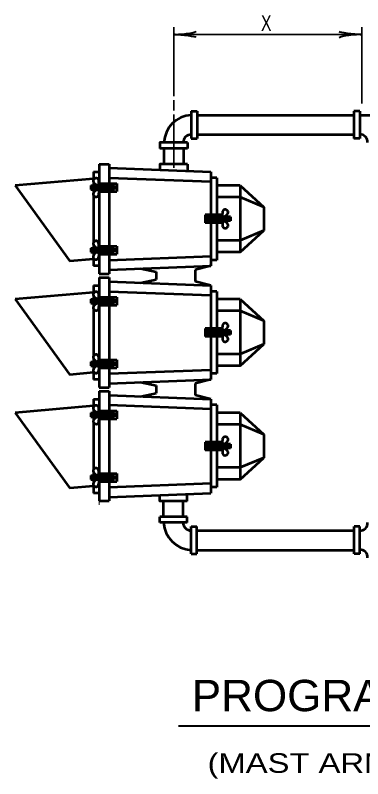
# Model space of a CAD drawing. Extents: x -370 to 486, y -203 to 341.
# Drawn here: x 133.3 to 186.5, y -16.9 to 100 of the extents above; entities that cross this region are included whole.
import ezdxf
from ezdxf.enums import TextEntityAlignment as Align

# ---------------------------------------------------------------- set-up
doc = ezdxf.new("R2010")
doc.units = 0
doc.header["$LTSCALE"] = 0.96
doc.layers.add('1', color=7, linetype='Continuous', lineweight=53)

msp = doc.modelspace()

# ---------------------------------------------------------------- linework, layer by layer
at = {"layer": '1', "lineweight": 35}
for p, q in [((157.5789, 98.1642), (157.5789, 87.6184)), ((186.3789, 98.1642), (186.3789, 86.455)), ((157.5789, 97.0382), (186.3789, 97.0382)), ((157.5789, 86.9742), (157.5789, 85.404)), ((157.5789, 84.8001), (157.5789, 76.6272))]:
    msp.add_line(p, q, dxfattribs=at)
at = {"layer": '1'}
for p, q in [((160.2789, 85.303), (160.2789, 81.103)), ((160.2789, 85.303), (161.1789, 85.303)), ((161.1789, 85.303), (161.1789, 81.103)), ((161.1789, 84.703), (185.1535, 84.703)), ((185.1535, 85.303), (185.1535, 81.103)), ((186.0535, 85.303), (185.1535, 85.303)), ((186.0535, 85.303), (186.0535, 81.103)), ((186.0535, 84.703), (191.2011, 84.703)), ((160.2789, 81.103), (161.1789, 81.103)), ((161.1789, 81.703), (185.1535, 81.703)), ((186.0535, 81.103), (185.1535, 81.103)), ((159.6789, 79.603), (155.4789, 79.603)), ((156.0789, 79.603), (156.0789, 77.203)), ((159.0789, 79.603), (159.0789, 77.203)), ((159.6789, 80.503), (159.6789, 79.603)), ((146.1789, 77.203), (147.6789, 77.203)), ((146.1789, 77.203), (146.1789, 74.203)), ((147.6789, 77.203), (147.6789, 74.203)), ((157.5789, 77.203), (157.5789, 77.1891)), ((159.6789, 77.203), (159.6789, 76.1415)), ((145.2789, 76.003), (146.1789, 76.003)), ((145.2789, 76.003), (145.2789, 74.7359)), ((147.6789, 76.603), (163.2789, 76.003)), ((163.2789, 76.003), (163.2789, 69.403)), ((145.2789, 74.953), (133.3246, 73.9071)), ((147.6789, 75.102), (163.2789, 74.502)), ((164.1789, 75.103), (163.2789, 75.103)), ((164.1789, 75.103), (164.1789, 69.403)), ((133.3246, 73.9071), (141.6926, 62.3392)), ((144.8916, 73.9042), (144.8916, 73.3042)), ((144.8916, 73.9042), (148.4916, 73.9042)), ((145.0416, 73.7542), (145.0416, 73.4542)), ((145.1916, 73.9042), (145.1916, 73.3042)), ((145.2789, 74.4457), (145.2789, 73.9042)), ((145.3416, 73.7542), (145.3416, 73.4542)), ((145.8098, 73.9042), (145.3827, 74.2812)), ((145.4916, 73.9042), (145.4916, 73.3042)), ((145.6416, 73.7542), (145.6416, 73.4542)), ((145.7916, 73.9042), (145.7916, 73.3042)), ((145.9416, 73.7542), (145.9416, 73.4542)), ((146.0587, 73.9042), (146.1045, 74.4477)), ((146.0916, 73.9042), (146.0916, 73.3042)), ((146.1789, 74.203), (148.8789, 74.203)), ((146.2416, 73.7542), (146.2416, 73.4542)), ((146.3916, 73.9042), (146.3916, 73.3042)), ((146.5416, 73.7542), (146.5416, 73.4542)), ((146.6916, 73.9042), (146.6916, 73.3042)), ((146.8416, 73.7542), (146.8416, 73.4542)), ((146.9916, 73.9042), (146.9916, 73.3042)), ((147.1416, 73.7542), (147.1416, 73.4542)), ((147.2916, 73.9042), (147.2916, 73.3042)), ((147.4416, 73.7542), (147.4416, 73.4542)), ((147.5916, 73.9042), (147.5916, 73.3042)), ((147.7416, 73.7542), (147.7416, 73.4542)), ((147.8916, 73.9042), (147.8916, 73.3042)), ((148.0416, 73.7542), (148.0416, 73.4542)), ((148.1916, 73.9042), (148.1916, 73.3042)), ((148.3416, 73.7542), (148.3416, 73.4542)), ((148.4916, 73.9042), (148.4916, 73.3042)), ((148.8789, 74.203), (148.8789, 73.003)), ((167.7789, 73.903), (164.1789, 73.903)), ((167.7789, 73.903), (167.7789, 63.703)), ((167.7789, 73.903), (171.3789, 70.603)), ((144.8916, 73.3042), (148.4916, 73.3042)), ((145.2789, 73.3042), (145.2789, 72.7641)), ((145.8098, 73.3056), (145.3827, 72.9286)), ((146.0587, 73.3056), (146.1045, 72.7621)), ((146.1789, 73.003), (148.8789, 73.003)), ((146.1789, 73.003), (146.1789, 64.603)), ((147.6789, 73.003), (147.6789, 64.603)), ((145.2789, 72.4739), (145.2789, 65.1543)), ((167.7789, 72.103), (164.1789, 72.103)), ((171.3789, 70.603), (167.7789, 72.103)), ((171.3789, 70.603), (171.3789, 67.003)), ((165.0865, 69.403), (162.3789, 69.403)), ((162.3789, 69.403), (162.3789, 68.203)), ((166.2789, 69.103), (162.6789, 69.103)), ((162.6789, 69.103), (162.6789, 68.503)), ((162.9789, 69.103), (162.9789, 68.503)), ((163.2789, 69.103), (163.2789, 68.503)), ((163.5789, 69.103), (163.5789, 68.503)), ((163.8789, 69.103), (163.8789, 68.503)), ((164.1789, 69.103), (164.1789, 68.503)), ((164.4789, 69.103), (164.4789, 68.503)), ((164.7789, 69.103), (164.7789, 68.503)), ((165.1118, 69.103), (165.066, 69.6465)), ((165.0789, 69.103), (165.0789, 68.503)), ((165.3607, 69.103), (165.7878, 69.48)), ((165.3789, 69.103), (165.3789, 68.503)), ((165.6789, 69.103), (165.6789, 68.503)), ((165.9789, 69.103), (165.9789, 68.503)), ((166.2789, 69.103), (166.2789, 68.503)), ((165.0789, 68.203), (162.3789, 68.203)), ((166.2789, 68.503), (162.6789, 68.503)), ((162.8289, 68.953), (162.8289, 68.653)), ((163.1289, 68.953), (163.1289, 68.653)), ((163.2789, 68.203), (163.2789, 61.603)), ((163.4289, 68.953), (163.4289, 68.653)), ((163.7289, 68.953), (163.7289, 68.653)), ((163.8789, 68.953), (163.8789, 68.653)), ((164.0289, 68.953), (164.0289, 68.653)), ((164.1789, 68.203), (164.1789, 62.503)), ((164.3289, 68.953), (164.3289, 68.653)), ((164.6289, 68.953), (164.6289, 68.653)), ((164.9289, 68.953), (164.9289, 68.653)), ((165.1118, 68.5044), (165.066, 67.9609)), ((165.2289, 68.953), (165.2289, 68.653)), ((165.3607, 68.5044), (165.7878, 68.1274)), ((165.5289, 68.953), (165.5289, 68.653)), ((165.8289, 68.953), (165.8289, 68.653)), ((166.1289, 68.953), (166.1289, 68.653)), ((167.7789, 63.703), (171.3789, 67.003)), ((171.3789, 67.003), (167.7789, 65.503)), ((167.7789, 65.503), (164.1789, 65.503)), ((145.2789, 64.8241), (145.2789, 64.3026)), ((145.8022, 64.3026), (145.3751, 64.6796)), ((146.0511, 64.3026), (146.0969, 64.8461)), ((146.1789, 64.603), (148.8789, 64.603)), ((148.8789, 64.603), (148.8789, 63.403)), ((144.884, 64.3026), (144.884, 63.7026)), ((144.884, 64.3026), (148.484, 64.3026)), ((144.884, 63.7026), (148.484, 63.7026)), ((145.034, 64.1526), (145.034, 63.8526)), ((145.184, 64.3026), (145.184, 63.7026)), ((145.2789, 63.7026), (145.2789, 63.1825)), ((145.334, 64.1526), (145.334, 63.8526)), ((145.8022, 63.704), (145.3751, 63.327)), ((145.484, 64.3026), (145.484, 63.7026)), ((145.634, 64.1526), (145.634, 63.8526)), ((145.784, 64.3026), (145.784, 63.7026)), ((145.934, 64.1526), (145.934, 63.8526)), ((146.0511, 63.704), (146.0969, 63.1605)), ((146.084, 64.3026), (146.084, 63.7026)), ((146.1789, 63.403), (148.8789, 63.403)), ((146.1789, 63.403), (146.1789, 60.403)), ((146.234, 64.1526), (146.234, 63.8526)), ((146.384, 64.3026), (146.384, 63.7026)), ((146.534, 64.1526), (146.534, 63.8526)), ((146.684, 64.3026), (146.684, 63.7026)), ((146.834, 64.1526), (146.834, 63.8526)), ((146.984, 64.3026), (146.984, 63.7026)), ((147.134, 64.1526), (147.134, 63.8526)), ((147.284, 64.3026), (147.284, 63.7026)), ((147.434, 64.1526), (147.434, 63.8526)), ((147.584, 64.3026), (147.584, 63.7026)), ((147.6789, 63.403), (147.6789, 60.403)), ((147.734, 64.1526), (147.734, 63.8526)), ((147.884, 64.3026), (147.884, 63.7026)), ((148.034, 64.1526), (148.034, 63.8526)), ((148.184, 64.3026), (148.184, 63.7026)), ((148.334, 64.1526), (148.334, 63.8526)), ((148.484, 64.3026), (148.484, 63.7026)), ((167.7789, 63.703), (164.1789, 63.703)), ((145.2789, 62.653), (141.6926, 62.3392)), ((145.2789, 62.8523), (145.2789, 61.603)), ((147.6789, 62.5041), (163.2789, 63.1041)), ((164.1789, 62.503), (163.2789, 62.503)), ((146.1789, 61.603), (145.2789, 61.603)), ((147.6789, 61.003), (163.2789, 61.603)), ((152.4753, 61.1875), (154.8777, 60.703)), ((163.2789, 61.603), (160.8777, 61.003)), ((160.8777, 61.003), (160.8777, 59.203)), ((146.1789, 60.403), (147.6789, 60.403)), ((146.1789, 59.803), (147.6789, 59.803)), ((146.1789, 59.803), (146.1789, 56.803)), ((147.6789, 59.803), (147.6789, 56.803)), ((154.8777, 60.703), (154.8777, 59.503)), ((145.2789, 58.603), (146.1789, 58.603)), ((145.2789, 58.603), (145.2789, 57.3359)), ((147.6789, 59.2031), (163.2789, 58.603)), ((152.4753, 59.0186), (154.8777, 59.503)), ((163.2789, 58.603), (160.8777, 59.203)), ((163.2789, 58.603), (163.2789, 52.003)), ((145.2789, 57.553), (133.3246, 56.5071)), ((147.6789, 57.702), (163.2789, 57.102)), ((164.1789, 57.703), (163.2789, 57.703)), ((164.1789, 57.703), (164.1789, 52.003)), ((133.3246, 56.5071), (141.6926, 44.9392)), ((144.8916, 56.5042), (144.8916, 55.9042)), ((144.8916, 56.5042), (148.4916, 56.5042)), ((145.0416, 56.3542), (145.0416, 56.0542)), ((145.1916, 56.5042), (145.1916, 55.9042)), ((145.2789, 57.0457), (145.2789, 56.5042)), ((145.3416, 56.3542), (145.3416, 56.0542)), ((145.8098, 56.5042), (145.3827, 56.8812)), ((145.4916, 56.5042), (145.4916, 55.9042)), ((145.6416, 56.3542), (145.6416, 56.0542)), ((145.7916, 56.5042), (145.7916, 55.9042)), ((145.9416, 56.3542), (145.9416, 56.0542)), ((146.0587, 56.5042), (146.1045, 57.0477)), ((146.0916, 56.5042), (146.0916, 55.9042)), ((146.1789, 56.803), (148.8789, 56.803)), ((146.2416, 56.3542), (146.2416, 56.0542)), ((146.3916, 56.5042), (146.3916, 55.9042)), ((146.5416, 56.3542), (146.5416, 56.0542)), ((146.6916, 56.5042), (146.6916, 55.9042)), ((146.8416, 56.3542), (146.8416, 56.0542)), ((146.9916, 56.5042), (146.9916, 55.9042)), ((147.1416, 56.3542), (147.1416, 56.0542)), ((147.2916, 56.5042), (147.2916, 55.9042)), ((147.4416, 56.3542), (147.4416, 56.0542)), ((147.5916, 56.5042), (147.5916, 55.9042)), ((147.7416, 56.3542), (147.7416, 56.0542)), ((147.8916, 56.5042), (147.8916, 55.9042)), ((148.0416, 56.3542), (148.0416, 56.0542)), ((148.1916, 56.5042), (148.1916, 55.9042)), ((148.3416, 56.3542), (148.3416, 56.0542)), ((148.4916, 56.5042), (148.4916, 55.9042)), ((148.8789, 56.803), (148.8789, 55.603)), ((167.7789, 56.503), (164.1789, 56.503)), ((167.7789, 56.503), (167.7789, 46.303)), ((167.7789, 56.503), (171.3789, 53.203)), ((144.8916, 55.9042), (148.4916, 55.9042)), ((145.2789, 55.9042), (145.2789, 55.3641)), ((145.2789, 55.0739), (145.2789, 47.7543)), ((145.8098, 55.9056), (145.3827, 55.5286)), ((146.0587, 55.9056), (146.1045, 55.3621)), ((146.1789, 55.603), (148.8789, 55.603)), ((146.1789, 55.603), (146.1789, 47.203)), ((147.6789, 55.603), (147.6789, 47.203)), ((167.7789, 54.703), (164.1789, 54.703)), ((171.3789, 53.203), (167.7789, 54.703)), ((171.3789, 53.203), (171.3789, 49.603)), ((165.0865, 52.003), (162.3789, 52.003)), ((162.3789, 52.003), (162.3789, 50.803)), ((166.2789, 51.703), (162.6789, 51.703)), ((162.6789, 51.703), (162.6789, 51.103)), ((162.8289, 51.553), (162.8289, 51.253)), ((162.9789, 51.703), (162.9789, 51.103)), ((163.1289, 51.553), (163.1289, 51.253)), ((163.2789, 51.703), (163.2789, 51.103)), ((163.4289, 51.553), (163.4289, 51.253)), ((163.5789, 51.703), (163.5789, 51.103)), ((163.7289, 51.553), (163.7289, 51.253)), ((163.8789, 51.703), (163.8789, 51.103)), ((163.8789, 51.553), (163.8789, 51.253)), ((164.0289, 51.553), (164.0289, 51.253)), ((164.1789, 51.703), (164.1789, 51.103)), ((164.3289, 51.553), (164.3289, 51.253)), ((164.4789, 51.703), (164.4789, 51.103)), ((164.6289, 51.553), (164.6289, 51.253)), ((164.7789, 51.703), (164.7789, 51.103)), ((164.9289, 51.553), (164.9289, 51.253)), ((165.1118, 51.703), (165.066, 52.2465)), ((165.0789, 51.703), (165.0789, 51.103)), ((165.2289, 51.553), (165.2289, 51.253)), ((165.3607, 51.703), (165.7878, 52.08)), ((165.3789, 51.703), (165.3789, 51.103)), ((165.5289, 51.553), (165.5289, 51.253)), ((165.6789, 51.703), (165.6789, 51.103)), ((165.8289, 51.553), (165.8289, 51.253)), ((165.9789, 51.703), (165.9789, 51.103)), ((166.1289, 51.553), (166.1289, 51.253)), ((166.2789, 51.703), (166.2789, 51.103)), ((165.0789, 50.803), (162.3789, 50.803)), ((166.2789, 51.103), (162.6789, 51.103)), ((163.2789, 50.803), (163.2789, 44.203)), ((164.1789, 50.803), (164.1789, 45.103)), ((165.1118, 51.1044), (165.066, 50.5609)), ((165.3607, 51.1044), (165.7878, 50.7274)), ((167.7789, 46.303), (171.3789, 49.603)), ((171.3789, 49.603), (167.7789, 48.103)), ((167.7789, 48.103), (164.1789, 48.103)), ((144.884, 46.9026), (144.884, 46.3026)), ((144.884, 46.9026), (148.484, 46.9026)), ((145.184, 46.9026), (145.184, 46.3026)), ((145.2789, 47.4241), (145.2789, 46.9026)), ((145.8022, 46.9026), (145.3751, 47.2796)), ((145.484, 46.9026), (145.484, 46.3026)), ((145.784, 46.9026), (145.784, 46.3026)), ((146.0511, 46.9026), (146.0969, 47.4461)), ((146.084, 46.9026), (146.084, 46.3026)), ((146.1789, 47.203), (148.8789, 47.203)), ((146.384, 46.9026), (146.384, 46.3026)), ((146.684, 46.9026), (146.684, 46.3026)), ((146.984, 46.9026), (146.984, 46.3026)), ((147.284, 46.9026), (147.284, 46.3026)), ((147.584, 46.9026), (147.584, 46.3026)), ((147.884, 46.9026), (147.884, 46.3026)), ((148.184, 46.9026), (148.184, 46.3026)), ((148.484, 46.9026), (148.484, 46.3026)), ((148.8789, 47.203), (148.8789, 46.003)), ((144.884, 46.3026), (148.484, 46.3026)), ((145.034, 46.7526), (145.034, 46.4526)), ((145.2789, 46.3026), (145.2789, 45.7825)), ((145.334, 46.7526), (145.334, 46.4526)), ((145.8022, 46.304), (145.3751, 45.927)), ((145.634, 46.7526), (145.634, 46.4526)), ((145.934, 46.7526), (145.934, 46.4526)), ((146.0511, 46.304), (146.0969, 45.7605)), ((146.1789, 46.003), (148.8789, 46.003)), ((146.1789, 46.003), (146.1789, 43.003)), ((146.234, 46.7526), (146.234, 46.4526)), ((146.534, 46.7526), (146.534, 46.4526)), ((146.834, 46.7526), (146.834, 46.4526)), ((147.134, 46.7526), (147.134, 46.4526)), ((147.434, 46.7526), (147.434, 46.4526)), ((147.6789, 46.003), (147.6789, 43.003)), ((147.6789, 45.1041), (163.2789, 45.7041)), ((147.734, 46.7526), (147.734, 46.4526)), ((148.034, 46.7526), (148.034, 46.4526)), ((148.334, 46.7526), (148.334, 46.4526)), ((167.7789, 46.303), (164.1789, 46.303)), ((145.2789, 45.253), (141.6926, 44.9392)), ((145.2789, 45.4523), (145.2789, 44.203)), ((164.1789, 45.103), (163.2789, 45.103)), ((146.1789, 44.203), (145.2789, 44.203)), ((147.6789, 43.603), (163.2789, 44.203)), ((152.4753, 43.7875), (154.8777, 43.303)), ((154.8777, 43.303), (154.8777, 42.103)), ((163.2789, 44.203), (160.8777, 43.603)), ((160.8777, 43.603), (160.8777, 41.803)), ((146.1789, 43.003), (147.6789, 43.003)), ((146.1789, 42.403), (147.6789, 42.403)), ((146.1789, 42.403), (146.1789, 39.403)), ((147.6789, 42.403), (147.6789, 39.403)), ((152.4753, 41.6186), (154.8777, 42.103)), ((145.2789, 41.203), (146.1789, 41.203)), ((145.2789, 41.203), (145.2789, 39.9359)), ((147.6789, 41.803), (163.2789, 41.203)), ((163.2789, 41.203), (160.8777, 41.803)), ((163.2789, 41.203), (163.2789, 34.603)), ((145.2789, 40.153), (133.3246, 39.1071)), ((147.6789, 40.302), (163.2789, 39.702)), ((164.1789, 40.303), (163.2789, 40.303)), ((164.1789, 40.303), (164.1789, 34.603)), ((133.3246, 39.1071), (141.6926, 27.5392)), ((144.8916, 39.1042), (144.8916, 38.5042)), ((144.8916, 39.1042), (148.4916, 39.1042)), ((145.0416, 38.9542), (145.0416, 38.6542)), ((145.1916, 39.1042), (145.1916, 38.5042)), ((145.2789, 39.6457), (145.2789, 39.1042)), ((145.3416, 38.9542), (145.3416, 38.6542)), ((145.8098, 39.1042), (145.3827, 39.4812)), ((145.4916, 39.1042), (145.4916, 38.5042)), ((145.6416, 38.9542), (145.6416, 38.6542)), ((145.7916, 39.1042), (145.7916, 38.5042)), ((145.9416, 38.9542), (145.9416, 38.6542)), ((146.0587, 39.1042), (146.1045, 39.6477)), ((146.0916, 39.1042), (146.0916, 38.5042)), ((146.1789, 39.403), (148.8789, 39.403)), ((146.2416, 38.9542), (146.2416, 38.6542)), ((146.3916, 39.1042), (146.3916, 38.5042)), ((146.5416, 38.9542), (146.5416, 38.6542)), ((146.6916, 39.1042), (146.6916, 38.5042)), ((146.8416, 38.9542), (146.8416, 38.6542)), ((146.9916, 39.1042), (146.9916, 38.5042)), ((147.1416, 38.9542), (147.1416, 38.6542)), ((147.2916, 39.1042), (147.2916, 38.5042)), ((147.4416, 38.9542), (147.4416, 38.6542)), ((147.5916, 39.1042), (147.5916, 38.5042)), ((147.7416, 38.9542), (147.7416, 38.6542)), ((147.8916, 39.1042), (147.8916, 38.5042)), ((148.0416, 38.9542), (148.0416, 38.6542)), ((148.1916, 39.1042), (148.1916, 38.5042)), ((148.3416, 38.9542), (148.3416, 38.6542)), ((148.4916, 39.1042), (148.4916, 38.5042)), ((148.8789, 39.403), (148.8789, 38.203)), ((167.7789, 39.103), (164.1789, 39.103)), ((167.7789, 39.103), (167.7789, 28.903)), ((167.7789, 39.103), (171.3789, 35.803)), ((144.8916, 38.5042), (148.4916, 38.5042)), ((145.2789, 38.5042), (145.2789, 37.9641)), ((145.2789, 37.6739), (145.2789, 30.3543)), ((145.8098, 38.5056), (145.3827, 38.1286)), ((146.0587, 38.5056), (146.1045, 37.9621)), ((146.1789, 38.203), (148.8789, 38.203)), ((146.1789, 38.203), (146.1789, 29.803)), ((147.6789, 38.203), (147.6789, 29.803)), ((167.7789, 37.303), (164.1789, 37.303)), ((171.3789, 35.803), (167.7789, 37.303)), ((171.3789, 35.803), (171.3789, 32.203)), ((165.0865, 34.603), (162.3789, 34.603)), ((162.3789, 34.603), (162.3789, 33.403)), ((166.2789, 34.303), (162.6789, 34.303)), ((162.6789, 34.303), (162.6789, 33.703)), ((162.8289, 34.153), (162.8289, 33.853)), ((162.9789, 34.303), (162.9789, 33.703)), ((163.1289, 34.153), (163.1289, 33.853)), ((163.2789, 34.303), (163.2789, 33.703)), ((163.4289, 34.153), (163.4289, 33.853)), ((163.5789, 34.303), (163.5789, 33.703)), ((163.7289, 34.153), (163.7289, 33.853)), ((163.8789, 34.303), (163.8789, 33.703)), ((163.8789, 34.153), (163.8789, 33.853)), ((164.0289, 34.153), (164.0289, 33.853)), ((164.1789, 34.303), (164.1789, 33.703)), ((164.3289, 34.153), (164.3289, 33.853)), ((164.4789, 34.303), (164.4789, 33.703)), ((164.6289, 34.153), (164.6289, 33.853)), ((164.7789, 34.303), (164.7789, 33.703)), ((164.9289, 34.153), (164.9289, 33.853)), ((165.1118, 34.303), (165.066, 34.8465)), ((165.0789, 34.303), (165.0789, 33.703)), ((165.2289, 34.153), (165.2289, 33.853)), ((165.3607, 34.303), (165.7878, 34.68)), ((165.3789, 34.303), (165.3789, 33.703)), ((165.5289, 34.153), (165.5289, 33.853)), ((165.6789, 34.303), (165.6789, 33.703)), ((165.8289, 34.153), (165.8289, 33.853)), ((165.9789, 34.303), (165.9789, 33.703)), ((166.1289, 34.153), (166.1289, 33.853)), ((166.2789, 34.303), (166.2789, 33.703)), ((165.0789, 33.403), (162.3789, 33.403)), ((166.2789, 33.703), (162.6789, 33.703)), ((163.2789, 33.403), (163.2789, 26.803)), ((164.1789, 33.403), (164.1789, 27.703)), ((165.1118, 33.7044), (165.066, 33.1609)), ((165.3607, 33.7044), (165.7878, 33.3274)), ((167.7789, 28.903), (171.3789, 32.203)), ((171.3789, 32.203), (167.7789, 30.703)), ((167.7789, 30.703), (164.1789, 30.703)), ((144.884, 29.5026), (144.884, 28.9026)), ((144.884, 29.5026), (148.484, 29.5026)), ((145.034, 29.3526), (145.034, 29.0526)), ((145.184, 29.5026), (145.184, 28.9026)), ((145.2789, 30.0241), (145.2789, 29.5026)), ((145.334, 29.3526), (145.334, 29.0526)), ((145.8022, 29.5026), (145.3751, 29.8796)), ((145.484, 29.5026), (145.484, 28.9026)), ((145.634, 29.3526), (145.634, 29.0526)), ((145.784, 29.5026), (145.784, 28.9026)), ((145.934, 29.3526), (145.934, 29.0526)), ((146.0511, 29.5026), (146.0969, 30.0461)), ((146.084, 29.5026), (146.084, 28.9026)), ((146.1789, 29.803), (148.8789, 29.803)), ((146.234, 29.3526), (146.234, 29.0526)), ((146.384, 29.5026), (146.384, 28.9026)), ((146.534, 29.3526), (146.534, 29.0526)), ((146.684, 29.5026), (146.684, 28.9026)), ((146.834, 29.3526), (146.834, 29.0526)), ((146.984, 29.5026), (146.984, 28.9026)), ((147.134, 29.3526), (147.134, 29.0526)), ((147.284, 29.5026), (147.284, 28.9026)), ((147.434, 29.3526), (147.434, 29.0526)), ((147.584, 29.5026), (147.584, 28.9026)), ((147.734, 29.3526), (147.734, 29.0526)), ((147.884, 29.5026), (147.884, 28.9026)), ((148.034, 29.3526), (148.034, 29.0526)), ((148.184, 29.5026), (148.184, 28.9026)), ((148.334, 29.3526), (148.334, 29.0526)), ((148.484, 29.5026), (148.484, 28.9026)), ((148.8789, 29.803), (148.8789, 28.603)), ((144.884, 28.9026), (148.484, 28.9026)), ((145.2789, 28.9026), (145.2789, 28.3825)), ((145.8022, 28.904), (145.3751, 28.527)), ((146.0511, 28.904), (146.0969, 28.3605)), ((146.1789, 28.603), (148.8789, 28.603)), ((146.1789, 28.603), (146.1789, 25.603)), ((147.6789, 28.603), (147.6789, 25.603)), ((147.6789, 27.7041), (163.2789, 28.3041)), ((167.7789, 28.903), (164.1789, 28.903)), ((145.2789, 27.853), (141.6926, 27.5392)), ((145.2789, 28.0523), (145.2789, 26.803)), ((164.1789, 27.703), (163.2789, 27.703)), ((146.1789, 26.803), (145.2789, 26.803)), ((147.6789, 26.203), (163.2789, 26.803)), ((159.6435, 25.5897), (159.6435, 26.6512)), ((146.1789, 25.603), (147.6789, 25.603)), ((156.0435, 23.1897), (156.0435, 25.5897)), ((159.0435, 23.1897), (159.0435, 25.5897)), ((159.6435, 23.1897), (155.4435, 23.1897)), ((155.4435, 22.2897), (155.4435, 23.1897)), ((159.6435, 22.2897), (155.4435, 22.2897)), ((159.6435, 22.2897), (159.6435, 23.1897)), ((160.2435, 17.4897), (160.2435, 21.6897)), ((160.2435, 21.6897), (161.1435, 21.6897)), ((161.1435, 17.4897), (161.1435, 21.6897)), ((161.1435, 21.0897), (185.1875, 21.0897)), ((185.1875, 17.4897), (185.1875, 21.6897)), ((186.0875, 21.6897), (185.1875, 21.6897)), ((186.0875, 17.4897), (186.0875, 21.6897)), ((161.1435, 18.0897), (185.1875, 18.0897)), ((160.2435, 17.4897), (161.1435, 17.4897)), ((186.0875, 17.4897), (185.1875, 17.4897))]:
    msp.add_line(p, q, dxfattribs=at)
at = {"layer": '1', "lineweight": 13}
msp.add_line((146.1789, 25.603), (146.1789, 25.003), dxfattribs=at)
at = {"layer": '1', "lineweight": 40}
msp.add_line((158.291, -8.8441), (237.5365, -8.8441), dxfattribs=at)
at = {"layer": '1'}
for points in [[(159.6789, 80.503), (155.4789, 80.503), (155.4789, 79.603)], [(159.6789, 77.203), (155.4789, 77.203), (155.4789, 76.303)], [(159.6435, 25.5897), (155.4435, 25.5897), (155.4435, 26.4897)]]:
    msp.add_lwpolyline(points, dxfattribs=at)
for centre, radius, start, end in [((160.5025, 80.2794), 4.4293, 92.89399, 177.10601), ((160.1978, 80.5841), 1.1218, 85.85174, 184.14826), ((186.1723, 80.6218), 1.0877, 353.73087, 96.26912), ((145.6915, 74.5908), 0.4373, 340.87038, 225.06771), ((145.6915, 72.619), 0.4373, 134.93229, 19.12962), ((165.479, 69.7896), 0.4373, 314.93229, 199.12962), ((165.479, 67.8178), 0.4373, 160.87038, 45.06771), ((145.6839, 64.9892), 0.4373, 340.87038, 225.06771), ((145.6839, 63.0174), 0.4373, 134.93229, 19.12962), ((145.6915, 57.1908), 0.4373, 340.87038, 225.06771), ((145.6915, 55.219), 0.4373, 134.93229, 19.12962), ((165.479, 52.3896), 0.4373, 314.93229, 199.12962), ((165.479, 50.4178), 0.4373, 160.87038, 45.06771), ((145.6839, 47.5892), 0.4373, 340.87038, 225.06771), ((145.6839, 45.6174), 0.4373, 134.93229, 19.12962), ((145.6915, 39.7908), 0.4373, 340.87038, 225.06771), ((145.6915, 37.819), 0.4373, 134.93229, 19.12962), ((165.479, 34.9896), 0.4373, 314.93229, 199.12962), ((165.479, 33.0178), 0.4373, 160.87038, 45.06771), ((145.6839, 30.1892), 0.4373, 340.87038, 225.06771), ((145.6839, 28.2174), 0.4373, 134.93229, 19.12962), ((160.4671, 22.5133), 4.4293, 182.89399, 267.10601), ((160.1624, 22.2086), 1.1218, 175.85174, 274.14826), ((186.1723, 22.179), 1.0877, 263.73087, 6.26912), ((186.1723, 17.0234), 1.0877, 353.73087, 96.26912)]:
    msp.add_arc(centre, radius, start, end, dxfattribs=at)
at = {"layer": '1', "lineweight": 40}
for centre, major_axis, ratio, start_param, end_param in [((158.8883, 97.3698), (-2.1428, -0.1874), 0.122415, 0.89635335, 3.14159265), ((158.8883, 97.3698), (-2.1428, -0.1874), 0.122415, 0.89635335, 3.14159265), ((185.0343, 97.2921), (2.1077, -0.2108), 0.07063, 3.14071475, 5.41810995), ((185.0343, 97.2921), (2.1077, -0.2108), 0.07063, 3.14071475, 5.41810995), ((158.9235, 96.7843), (-2.1077, 0.2108), 0.07063, 3.14071475, 5.41810995), ((158.9235, 96.7843), (-2.1077, 0.2108), 0.07063, 3.14071475, 5.41810995), ((185.0695, 96.7066), (2.1428, 0.1874), 0.122415, 0.89635335, 3.14159265), ((185.0695, 96.7066), (2.1428, 0.1874), 0.122415, 0.89635335, 3.14159265)]:
    msp.add_ellipse(centre, major_axis=major_axis, ratio=ratio, start_param=start_param, end_param=end_param, dxfattribs=at)

# ---------------------------------------------------------------- texts
at = {"layer": '1'}
for s, height, width, p in [('X', 2.4, 0.75, (171.751, 97.5832)), ('PROGRAMMED HEADS', 4.8, 1.05, (197.7977, -6.5913)), ('(MAST ARM - BACK TO BACK)', 3, 1.25, (198.4272, -16.032))]:
    msp.add_text(s, height=height, dxfattribs=dict(at, width=width)).set_placement(p, align=Align.CENTER)

doc.saveas('drawing.dxf')
